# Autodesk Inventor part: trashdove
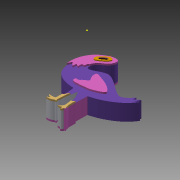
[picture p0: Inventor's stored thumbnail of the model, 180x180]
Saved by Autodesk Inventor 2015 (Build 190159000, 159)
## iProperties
Created: 2017-04
Part Number: trashdove
Material: Generisch
Document SubType Name: Modeling
Designer: Andreas
Density: 1 g/cm^3
Appearance: Vorgabe
Author: Andreas
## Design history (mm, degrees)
sketch "Skizze1"
  geometry: L1 (0, 0)-(123.924, 0); L2 (123.924, 0)-(123.924, -103.291); L3 (123.924, -103.291)-(0, -103.291); L4 (0, -103.291)-(0, 0); L5 (100.24, -39.328)-(100.181, -39.999); L6 (100.181, -39.999)-(100.071, -40.816); L7 (100.071, -40.816)-(99.989, -41.524); L8 (99.989, -41.524)-(99.898, -42.291); L9 (99.898, -42.291)-(99.761, -42.766); L10 (99.761, -42.766)-(99.665, -43.067); L11 (99.665, -43.067)-(99.665, -43.227); L12 (99.665, -43.227)-(99.989, -43.14); L13 (99.989, -43.14)-(100.404, -42.793); L14 (100.404, -42.793)-(101.158, -42.213); L15 (101.158, -42.213)-(101.728, -41.748); L16 (101.728, -41.748)-(102.719, -41.077); L17 (102.719, -41.077)-(103.463, -40.542); L18 (103.463, -40.542)-(104.175, -39.981); L19 (104.175, -39.981)-(104.686, -39.511); L20 (104.686, -39.511)-(105.024, -39.223); L21 (105.024, -39.223)-(105.275, -39.027); L22 (105.275, -39.027)-(105.558, -38.799); L23 (105.558, -38.799)-(105.672, -38.716); L24 (105.672, -38.716)-(105.513, -39.237); L25 (105.513, -39.237)-(105.129, -40.118); L26 (105.129, -40.118)-(104.705, -41.003); L27 (104.705, -41.003)-(104.116, -42.104); L28 (104.116, -42.104)-(103.783, -42.693); L29 (103.783, -42.693)-(103.413, -43.24); L30 (103.413, -43.24)-(102.965, -43.784); L31 (102.965, -43.784)-(102.792, -43.939); L32 (102.792, -43.939)-(102.751, -44.121); L33 (102.751, -44.121)-(102.751, -44.208); L34 (102.751, -44.208)-(103.048, -44.158); L35 (103.048, -44.158)-(103.481, -43.902); L36 (103.481, -43.902)-(104.171, -43.382); L37 (104.171, -43.382)-(105.029, -42.843); L38 (105.029, -42.843)-(105.672, -42.387); L39 (105.672, -42.387)-(106.083, -42.14); L40 (106.083, -42.14)-(106.494, -41.857); L41 (106.494, -41.857)-(106.786, -41.679); L42 (106.786, -41.679)-(106.996, -41.647); L43 (106.996, -41.647)-(106.677, -42.41); L44 (106.677, -42.41)-(106.092, -43.263); L45 (106.092, -43.263)-(105.449, -44.226); L46 (105.449, -44.226)-(104.718, -45.29); L47 (104.718, -45.29)-(104.116, -46.121); L48 (104.116, -46.121)-(103.385, -47.048); L49 (103.385, -47.048)-(102.737, -47.883); L50 (102.737, -47.883)-(102.048, -48.654); L51 (102.048, -48.654)-(101.094, -49.709); L52 (101.094, -49.709)-(100.295, -50.549); L53 (100.295, -50.549)-(99.336, -51.444); L54 (99.336, -51.444)-(98.766, -52.001); L55 (98.766, -52.001)-(97.478, -53.146); L56 (97.478, -53.146)-(96.355, -54.087); L57 (96.355, -54.087)-(95.383, -54.89); L58 (95.383, -54.89)-(94.758, -55.301); L59 (94.758, -55.301)-(92.448, -57.004); L60 (92.448, -57.004)-(91.411, -57.689); L61 (91.411, -57.689)-(90.375, -58.346); L62 (90.375, -58.346)-(88.777, -59.35); L63 (88.777, -59.35)-(87.572, -60.085); L64 (87.572, -60.085)-(86.39, -60.733)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; 116 further points; 1 other entity
  constraints: 10 end point, 4 horizontal, 2 vertical, 127 other
  node "Bild1"
sketch "Skizze2"
  geometry: 57 further points
  constraints: 56 other
extrude "Extrusion1" new body sketch "Skizze1" distance "d30" = 20; taper "d31" = 0 deg
sketch "Skizze3"
  geometry: L1 (38.917, -15.033)-(39.465, -10.173); L2 (39.465, -10.173)-(43.076, -13.159); 4 further points
  constraints: 4 end point, 2 other
extrude "Extrusion2" join sketch "Skizze3" distance "d42" = 20; taper "d43" = 0 deg
workplane "Arbeitsebene1"
sketch "Skizze10"
  geometry: 185 further points
  constraints: 187 other
sketch "Skizze4"
  geometry: 67 further points
  constraints: 66 other
sketch "Skizze5"
  geometry: 51 further points
  constraints: 50 other
extrude "Extrusion3" join sketch "Skizze2" distance "d44" = 2; taper "d45" = 0 deg
extrude "Extrusion4" join sketch "Skizze5" distance "d46" = 2; taper "d47" = 0 deg
sketch "Skizze6"
  geometry: 1 further point
extrude "Extrusion5" join sketch "Skizze4" distance "d48" = 3; taper "d49" = 0 deg
sketch "Skizze7"
  geometry: 8 further points
  constraints: 6 other
extrude "Extrusion6" join sketch "Skizze7" distance "d50" = 3; taper "d51" = 0 deg
sketch "Skizze8"
  geometry: 2 further points
  constraints: 1 other
extrude "Extrusion7" join sketch "Skizze8" distance "d52" = 2; taper "d53" = 0 deg
sketch "Skizze9"
  geometry: 13 further points
  constraints: 7 other
extrude "Extrusion8" join sketch "Skizze9" distance "d54" = 2; taper "d55" = 0 deg
extrude "Extrusion9" join sketch "Skizze10" stored distance "d57" = 20; taper "d58" = 0 deg
sketch "Skizze13"
  geometry: 21 further points
  constraints: 23 other
extrude "Extrusion10" join sketch "Skizze13" distance "d59" = 2; taper "d60" = 0 deg
sketch "Skizze14"
  geometry: 9 further points
  constraints: 5 other
extrude "Extrusion11" join sketch "Skizze14" distance "d61" = 2; taper "d62" = 0 deg
node "Volumenkörper1"
